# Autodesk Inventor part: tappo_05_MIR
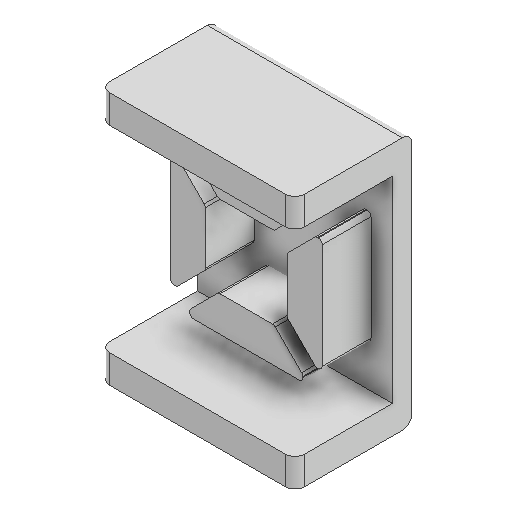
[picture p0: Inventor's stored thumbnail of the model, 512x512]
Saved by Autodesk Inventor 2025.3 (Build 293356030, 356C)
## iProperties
Created: 2026-02
Part Number: tappo_05_MIR
Material: Generico
Document SubType Name: Modeling
Designer: R5800u
Density: 1 g/cm^3
Appearance: Default
Author: R5800u
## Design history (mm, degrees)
derived "tappo_05.ipt"
  sketch "Schizzo1"
    geometry: L1 (-10, 10)-(10, 10) reference; L2 (10, 10)-(10, -10) reference; L3 (10, -10)-(-10, -10) reference; L4 (-10, -10)-(-10, 10) reference; L5 (-10, 10)-(10, -10) reference; L6 (10, 10)-(-10, -10) reference; L7 (-6, -8)-(-3, -8) reference; L8 (-6, -7.061)-(-6, -8) reference; L9 (-2.939, -4)-(-6, -7.061) reference; L10 (0, 0)-(0, -10) reference; L11 (-2.939, -4)-(0, -4) reference; L12 (-3, -8)-(0, -8) reference; L13 (0, -7.8)-(-3, -7.8) reference; L14 (-3, -7.8)-(-5.8, -7.8) reference; L15 (-5.8, -7.8)-(-5.8, -7.144) reference; L16 (-5.8, -7.144)-(-2.856, -4.2) reference; L17 (-2.856, -4.2)-(0, -4.2) reference; L18 (0, -7.8)-(3, -7.8) reference; L19 (3, -7.8)-(5.8, -7.8) reference; L20 (5.8, -7.8)-(5.8, -7.144) reference; L21 (5.8, -7.144)-(2.856, -4.2) reference; L22 (2.856, -4.2)-(0, -4.2) reference
  sketch "Schizzo2"
    geometry: 1 further point
  sketch "Schizzo3"
    geometry: L1 (0, 0)-(-20, 0) reference; L2 (-20, 0)-(-20, 2) reference; L3 (0, 2)-(-20, 2) reference; L4 (0, 0)-(0, 2) reference; 1 further point
  sketch "Schizzo4"
    geometry: L1 (10, -13)-(-10, -13) reference; L2 (10, 10)-(10, -13) reference; L3 (-10, -13)-(10, -13) reference; L4 (10, -13)-(10, -10.1) reference; L5 (10, -10.1)-(-10, -10.1) reference; L6 (-10, -10.1)-(-10, -13) reference; 2 further points
feature "Solido1::tappo_05.ipt"
feature "Solido2::tappo_05.ipt"
tag "Lavorazione contrassegno1"
node "Solido1"
node "Solido2"
